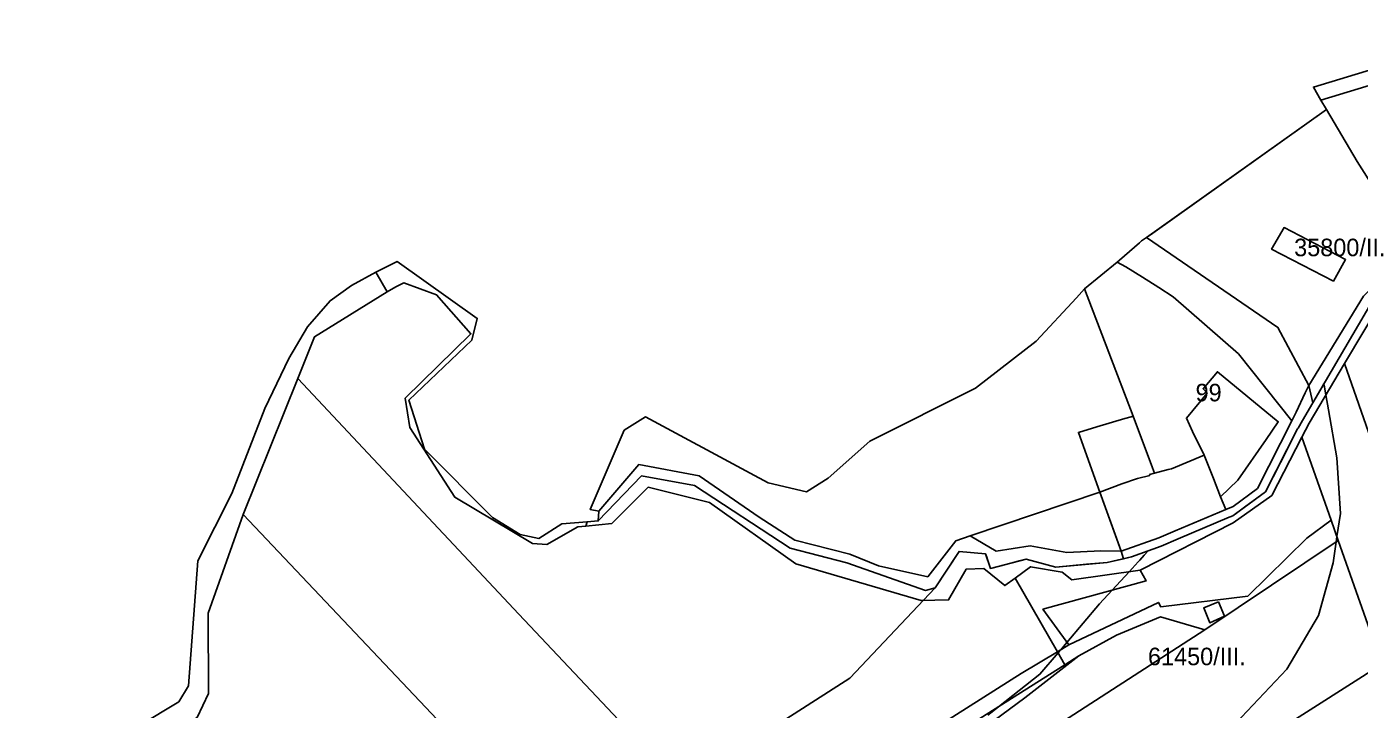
# Model space of a CAD drawing. Extents: x -522079 to -518833, y -1142400 to -1139961.
# Drawn here: x -521365.3 to -520985.3, y -1140287.7 to -1140093 of the extents above; entities that cross this region are included whole.
import ezdxf

# ---------------------------------------------------------------- set-up
doc = ezdxf.new("R2010")
doc.units = 0
for name, color, linetype in [('95560013', 7, 'Continuous'), ('95590013', 7, 'Continuous'), ('95600013', 7, 'Continuous'), ('95610013', 7, 'Continuous'), ('95630013', 7, 'Continuous'), ('95640013', 7, 'Continuous'), ('95660013', 7, 'Continuous')]:
    doc.layers.add(name, color=color, linetype=linetype)

msp = doc.modelspace()

# ---------------------------------------------------------------- linework, layer by layer
at = {"layer": '95560013'}
for points in [[(-520875.21, -1140149), (-520981.4, -1140212.45), (-520989.57, -1140189.1), (-520978.85, -1140171.05), (-520967.99, -1140160), (-520949.73, -1140132.35), (-520942.17, -1140125.91), (-520910.05, -1140126.02), (-520892.49, -1140129.42), (-520884.78, -1140137.14), (-520873.63, -1140145.32), (-520873.12, -1140147.75)], [(-521144.75, -1140380.49), (-521166.55, -1140356.84), (-521138.04, -1140336), (-521105.44, -1140313.39), (-521071.25, -1140292.13), (-521029.36, -1140265.01), (-520991.34, -1140239.5), (-520978.89, -1140274.79)], [(-521042, -1140261.25), (-521029.36, -1140265.01), (-521071.25, -1140292.13), (-521105.44, -1140313.39), (-521138.04, -1140336), (-521166.55, -1140356.84), (-521170.88, -1140360.01), (-521186.8, -1140371.65), (-521202.24, -1140382.94), (-521262.52, -1140430.5), (-521393.25, -1140533.65), (-521431, -1140563.44), (-521501.14, -1140618.78), (-521510.5, -1140608.85), (-521177.32, -1140348.18), (-521127.62, -1140312.94), (-521125.23, -1140315.3), (-521106.97, -1140303.78), (-521080.73, -1140284.42), (-521065.28, -1140272.43), (-521054.61, -1140266.48)], [(-521113.39, -1140302.86), (-521069.26, -1140274.95), (-521065.28, -1140272.43), (-521080.73, -1140284.42), (-521106.97, -1140303.78), (-521125.23, -1140315.3), (-521127.62, -1140312.94)], [(-520943.46, -1140405.56), (-520937.19, -1140417.44), (-520924.28, -1140409.64), (-520923.06, -1140411.9), (-520913.58, -1140428.33), (-520906.37, -1140439.12), (-521031.07, -1140496.4), (-521039.03, -1140495.22), (-521144.75, -1140380.49), (-520978.89, -1140274.79), (-520959.74, -1140329.07), (-520948.85, -1140357.77), (-520931.92, -1140395.43), (-520930.52, -1140398.04)]]:
    msp.add_lwpolyline(points, close=True, dxfattribs=at)
at = {"layer": '95590013'}
for points in [[(-521042.61, -1140257.18), (-521068.15, -1140269.31), (-521075.53, -1140259.14), (-521046.13, -1140251.03), (-521047.85, -1140248.01), (-521021.33, -1140234.46), (-521010.26, -1140226.65), (-521001.72, -1140210.08), (-520993.36, -1140233.77), (-521000.33, -1140238.84), (-521017.12, -1140255.44), (-521041.88, -1140258.46)], [(-521053.25, -1140242.58), (-521058.99, -1140242.45), (-521068.77, -1140242.91), (-521079.19, -1140241.03), (-521088.86, -1140242.57), (-521096.26, -1140238.22), (-521059.29, -1140225.79)]]:
    msp.add_lwpolyline(points, close=True, dxfattribs=at)
at = {"layer": '95600013'}
for points in [[(-520999.73, -1140195.29), (-521008.55, -1140178.79), (-521045.99, -1140153.16), (-520994.7, -1140116.62), (-520985.99, -1140131.48), (-520970.51, -1140155.67), (-520977.56, -1140163.28), (-520984.14, -1140169.84)], [(-521006.77, -1140150.28), (-521010.35, -1140156.42), (-520992.72, -1140165.55), (-520989.25, -1140159.42)], [(-521146.28, -1140239.39), (-521156.43, -1140232.87), (-521173.55, -1140221.12), (-521190.8, -1140217.9), (-521202.15, -1140231.14), (-521204.62, -1140230.71), (-521194.92, -1140208.09), (-521188.9, -1140204.31), (-521159.02, -1140220.32), (-521153.92, -1140223.1), (-521142.98, -1140225.64), (-521136.78, -1140221.72), (-521124.89, -1140211.23), (-521094.81, -1140196.05), (-521077.51, -1140182.69), (-521066.01, -1140170.35), (-521063.7, -1140167.77), (-521049.86, -1140204.08), (-521050.38, -1140204.23), (-521052.23, -1140204.77), (-521060.17, -1140207.15), (-521065.43, -1140208.69), (-521059.29, -1140225.79), (-521096.26, -1140238.22), (-521100.42, -1140239.62), (-521108.36, -1140249.87), (-521122.43, -1140246.78), (-521130.62, -1140243.41)]]:
    msp.add_lwpolyline(points, close=True, dxfattribs=at)
at = {"layer": '95610013'}
msp.add_lwpolyline([(-521160.13, -1140329.24), (-521224.97, -1140260.52), (-521288.02, -1140193.37), (-521283.26, -1140181.41), (-521262.49, -1140168.67), (-521260.08, -1140167.19), (-521257.73, -1140166.05), (-521248.42, -1140169.45), (-521238.63, -1140180.63), (-521257.36, -1140198.93), (-521256.03, -1140207.29), (-521243.23, -1140227.2), (-521221.12, -1140240.34), (-521217.02, -1140240.66), (-521208.19, -1140235.66), (-521205.87, -1140235.43), (-521198.5, -1140234.71), (-521188.13, -1140224.34), (-521170.61, -1140228.65), (-521146.04, -1140246.18), (-521110.27, -1140256.62), (-521102.44, -1140256.49), (-521097.42, -1140247.68), (-521092.43, -1140247.55), (-521086.36, -1140252.38), (-521083.46, -1140250.25), (-521071.39, -1140271.24), (-521081.77, -1140277.41), (-521115.76, -1140299)], dxfattribs=at)
for points in [[(-521303.57, -1140232.09), (-521288.02, -1140193.37), (-521224.97, -1140260.52), (-521160.13, -1140329.24), (-521181.05, -1140344.19), (-521190.73, -1140351.49), (-521249.83, -1140288.83)], [(-521319.77, -1140291.98), (-521316.7, -1140289.98), (-521313.45, -1140283.14), (-521313.53, -1140260.28), (-521303.57, -1140232.09), (-521249.83, -1140288.83), (-521190.73, -1140351.49), (-521212.85, -1140368.17), (-521233.39, -1140383.74), (-521281.93, -1140333.33)]]:
    msp.add_lwpolyline(points, close=True, dxfattribs=at)
at = {"layer": '95630013'}
for points in [[(-520840.13, -1140106.03), (-520833.95, -1140124.09), (-520832.38, -1140130.38), (-520834.57, -1140131.44), (-520836.28, -1140125.74), (-520838.47, -1140119.76), (-520853.61, -1140106.69), (-520870.57, -1140104.77), (-520896.13, -1140105.14), (-520930.39, -1140100.03), (-520964.33, -1140104.24), (-520996.26, -1140113.95), (-520998.41, -1140110.24), (-520941.45, -1140093.01), (-520920.41, -1140096.1), (-520898.59, -1140102.13), (-520887.39, -1140102.82), (-520865.88, -1140095.27), (-520850.56, -1140096.88)], [(-521212.75, -1140234.73), (-521205.52, -1140234.19), (-521205.87, -1140235.43), (-521208.19, -1140235.66), (-521217.02, -1140240.66), (-521221.12, -1140240.34), (-521243.23, -1140227.2), (-521256.03, -1140207.29), (-521257.36, -1140198.93), (-521238.63, -1140180.63), (-521248.42, -1140169.45), (-521257.73, -1140166.05), (-521260.08, -1140167.19), (-521262.49, -1140168.67), (-521265.75, -1140163.05), (-521259.67, -1140159.99), (-521236.81, -1140176.19), (-521238.42, -1140182.36), (-521256.3, -1140199.5), (-521251.89, -1140213.49), (-521232.49, -1140232.94), (-521224.62, -1140237.78), (-521219.26, -1140238.96)]]:
    msp.add_lwpolyline(points, close=True, dxfattribs=at)
for points in [[(-521333.16, -1140292.26), (-521321.89, -1140285.5), (-521319.14, -1140281.01), (-521316.46, -1140245.31), (-521306.79, -1140226.13), (-521297.37, -1140201.85), (-521290.54, -1140187.61), (-521285.21, -1140178.6), (-521278.81, -1140171.17), (-521272.67, -1140166.78), (-521265.75, -1140163.05), (-521262.49, -1140168.67), (-521283.26, -1140181.41), (-521288.02, -1140193.37), (-521303.57, -1140232.09), (-521313.53, -1140260.28), (-521313.45, -1140283.14), (-521316.7, -1140289.98)], [(-520978.85, -1140171.05), (-520989.57, -1140189.1), (-520999.64, -1140206.05), (-521001.72, -1140210.08), (-521010.26, -1140226.65), (-521021.33, -1140234.46), (-521047.85, -1140248.01), (-521067.28, -1140250.75), (-521070.02, -1140248.6), (-521079.08, -1140247.03), (-521083.46, -1140250.25), (-521086.36, -1140252.38), (-521092.43, -1140247.55), (-521097.42, -1140247.68), (-521102.44, -1140256.49), (-521110.27, -1140256.62), (-521146.04, -1140246.18), (-521170.61, -1140228.65), (-521188.13, -1140224.34), (-521198.5, -1140234.71), (-521205.87, -1140235.43), (-521205.52, -1140234.19), (-521202.32, -1140233.95), (-521189.97, -1140221.12), (-521174.85, -1140223.86), (-521147.64, -1140241.68), (-521131.5, -1140245.93), (-521109, -1140253.76), (-521106.23, -1140253.05), (-521099.45, -1140242.66), (-521091.88, -1140243.35), (-521090.52, -1140247.47), (-521080.35, -1140244.81), (-521071.82, -1140247.15), (-521057.24, -1140245.77), (-521050.32, -1140244.21), (-521041.79, -1140241.11), (-521036.95, -1140239.06), (-521022.45, -1140232.92), (-521021.42, -1140232.48), (-521012.11, -1140225.69), (-521002.93, -1140207.73), (-521002.8, -1140207.48), (-521001.55, -1140205.34), (-520998.6, -1140200.31), (-520997.26, -1140198.03), (-520981.64, -1140171.39)], [(-520981.64, -1140171.39), (-520997.26, -1140198.03), (-520998.6, -1140200.31), (-521001.55, -1140205.34), (-521002.8, -1140207.48), (-521002.93, -1140207.73), (-521012.11, -1140225.69), (-521021.42, -1140232.48), (-521022.45, -1140232.92), (-521036.95, -1140239.06), (-521041.79, -1140241.11), (-521050.32, -1140244.21), (-521057.24, -1140245.77), (-521071.82, -1140247.15), (-521080.35, -1140244.81), (-521090.52, -1140247.47), (-521091.88, -1140243.35), (-521099.45, -1140242.66), (-521106.23, -1140253.05), (-521109, -1140253.76), (-521131.5, -1140245.93), (-521147.64, -1140241.68), (-521174.85, -1140223.86), (-521189.97, -1140221.12), (-521202.32, -1140233.95), (-521202.15, -1140231.14), (-521190.8, -1140217.9), (-521173.55, -1140221.12), (-521156.43, -1140232.87), (-521146.28, -1140239.39), (-521130.62, -1140243.41), (-521122.43, -1140246.78), (-521108.36, -1140249.87), (-521100.42, -1140239.62), (-521096.26, -1140238.22), (-521088.86, -1140242.57), (-521079.19, -1140241.03), (-521068.77, -1140242.91), (-521058.99, -1140242.45), (-521053.25, -1140242.58), (-521042.48, -1140238.76), (-521037.86, -1140236.76), (-521023.4, -1140230.68), (-521021.33, -1140229.82), (-521014.41, -1140224.73), (-521004.56, -1140205.45), (-521003.35, -1140202.91), (-521000.75, -1140197.43), (-520999.73, -1140195.29), (-520984.14, -1140169.84)]]:
    msp.add_lwpolyline(points, dxfattribs=at)
at = {"layer": '95640013'}
for points in [[(-520985.99, -1140131.48), (-520994.7, -1140116.62), (-520996.26, -1140113.95), (-520964.33, -1140104.24), (-520930.39, -1140100.03), (-520896.13, -1140105.14), (-520870.57, -1140104.77), (-520853.61, -1140106.69), (-520838.47, -1140119.76), (-520836.28, -1140125.74), (-520840.13, -1140128.04), (-520870.79, -1140146.36), (-520871.38, -1140143.8), (-520882.74, -1140135.78), (-520891.9, -1140126.87), (-520912.67, -1140122.89), (-520943.89, -1140122.58), (-520951.79, -1140130), (-520969.72, -1140157.28), (-520970.51, -1140155.67)], [(-520989.25, -1140159.42), (-520992.72, -1140165.55), (-521010.35, -1140156.42), (-521006.77, -1140150.28)], [(-521019.82, -1140186.27), (-521038.45, -1140170.03), (-521042.52, -1140167.42), (-521047.19, -1140164.44), (-521051.86, -1140161.45), (-521054.36, -1140160.13), (-521053.72, -1140159.58), (-521048.05, -1140154.68), (-521047.4, -1140154.12), (-521045.99, -1140153.16), (-521008.55, -1140178.79), (-520999.73, -1140195.29), (-521000.75, -1140197.43), (-521003.35, -1140202.91), (-521004.56, -1140205.45)], [(-521043.73, -1140220.34), (-521044.31, -1140218.8), (-521049.86, -1140204.08), (-521063.7, -1140167.77), (-521054.36, -1140160.13), (-521051.86, -1140161.45), (-521047.19, -1140164.44), (-521042.52, -1140167.42), (-521038.45, -1140170.03), (-521019.82, -1140186.27), (-521004.56, -1140205.45), (-521014.41, -1140224.73), (-521021.33, -1140229.82), (-521023.4, -1140230.68), (-521024.94, -1140227.06), (-521019.95, -1140222.33), (-521011.89, -1140210.69), (-521008.43, -1140205.69), (-521025.79, -1140191.41), (-521029.89, -1140196.26), (-521028.73, -1140197.48), (-521034.61, -1140204.63), (-521032.9, -1140208.45), (-521029.59, -1140215.24), (-521038.87, -1140219.06), (-521039.84, -1140219.26)], [(-521034.61, -1140204.63), (-521028.73, -1140197.48), (-521029.89, -1140196.26), (-521025.79, -1140191.41), (-521008.43, -1140205.69), (-521011.89, -1140210.69), (-521019.95, -1140222.33), (-521024.94, -1140227.06), (-521026.94, -1140221.87), (-521029.59, -1140215.24), (-521032.9, -1140208.45)], [(-521059.29, -1140225.79), (-521065.43, -1140208.69), (-521060.17, -1140207.15), (-521052.23, -1140204.77), (-521050.38, -1140204.23), (-521049.86, -1140204.08), (-521044.31, -1140218.8), (-521043.73, -1140220.34), (-521045.13, -1140220.72), (-521045.07, -1140220.96), (-521048.62, -1140221.83), (-521053.03, -1140223.33)], [(-521045.13, -1140220.72), (-521043.73, -1140220.34), (-521039.84, -1140219.26), (-521038.87, -1140219.06), (-521029.59, -1140215.24), (-521026.94, -1140221.87), (-521024.94, -1140227.06), (-521023.4, -1140230.68), (-521037.86, -1140236.76), (-521042.48, -1140238.76), (-521053.25, -1140242.58), (-521059.29, -1140225.79), (-521053.03, -1140223.33), (-521048.62, -1140221.83), (-521045.07, -1140220.96)], [(-521029.36, -1140265.01), (-521042, -1140261.25), (-521054.61, -1140266.48), (-521065.28, -1140272.43), (-521069.26, -1140274.95), (-521071.39, -1140271.24), (-521068.15, -1140269.31), (-521042.61, -1140257.18), (-521041.88, -1140258.46), (-521017.12, -1140255.44), (-521000.33, -1140238.84), (-520993.36, -1140233.77), (-520991.34, -1140239.5)], [(-521071.39, -1140271.24), (-521083.46, -1140250.25), (-521079.08, -1140247.03), (-521070.02, -1140248.6), (-521067.28, -1140250.75), (-521047.85, -1140248.01), (-521046.13, -1140251.03), (-521075.53, -1140259.14), (-521068.15, -1140269.31)], [(-521025.45, -1140257.06), (-521023.8, -1140261.15), (-521027.96, -1140262.97), (-521029.71, -1140258.76)], [(-521025.45, -1140257.06), (-521029.71, -1140258.76), (-521027.96, -1140262.97), (-521023.8, -1140261.15)], [(-521115.76, -1140299), (-521081.77, -1140277.41), (-521071.39, -1140271.24), (-521069.26, -1140274.95), (-521113.39, -1140302.86), (-521127.62, -1140312.94), (-521130.86, -1140309.33)]]:
    msp.add_lwpolyline(points, close=True, dxfattribs=at)
msp.add_lwpolyline([(-520978.89, -1140274.79), (-520991.34, -1140239.5), (-520993.36, -1140233.77), (-521001.72, -1140210.08), (-520999.64, -1140206.05), (-520989.57, -1140189.1), (-520981.4, -1140212.45)], dxfattribs=at)
at = {"layer": '95660013'}
for points in [[(-520970.51, -1140155.67), (-520985.99, -1140131.48), (-520994.7, -1140116.62), (-520996.26, -1140113.95), (-520998.41, -1140110.24), (-520941.45, -1140093.01)], [(-521333.16, -1140292.26), (-521321.89, -1140285.5), (-521319.14, -1140281.01), (-521316.46, -1140245.31), (-521306.79, -1140226.13), (-521297.37, -1140201.85), (-521290.54, -1140187.61), (-521285.21, -1140178.6), (-521278.81, -1140171.17), (-521272.67, -1140166.78), (-521265.75, -1140163.05), (-521259.67, -1140159.99), (-521236.81, -1140176.19), (-521238.42, -1140182.36), (-521256.3, -1140199.5), (-521251.89, -1140213.49), (-521232.49, -1140232.94), (-521224.62, -1140237.78), (-521219.26, -1140238.96), (-521212.75, -1140234.73), (-521205.52, -1140234.19), (-521202.32, -1140233.95), (-521202.15, -1140231.14), (-521204.62, -1140230.71), (-521194.92, -1140208.09), (-521188.9, -1140204.31), (-521159.02, -1140220.32), (-521153.92, -1140223.1), (-521142.98, -1140225.64), (-521136.78, -1140221.72), (-521124.89, -1140211.23), (-521094.81, -1140196.05), (-521077.51, -1140182.69), (-521066.01, -1140170.35), (-521063.7, -1140167.77), (-521049.86, -1140204.08), (-521050.38, -1140204.23), (-521052.23, -1140204.77), (-521060.17, -1140207.15), (-521065.43, -1140208.69), (-521059.29, -1140225.79), (-521055.82, -1140235.43), (-521053.25, -1140242.58), (-521052.54, -1140244.71), (-521057.24, -1140245.77), (-521063.1, -1140246.32), (-521071.82, -1140247.15), (-521075.39, -1140246.17), (-521080.35, -1140244.81), (-521082.35, -1140245.33), (-521083.25, -1140245.57), (-521087.96, -1140246.8), (-521090.52, -1140247.47), (-521091.26, -1140245.22), (-521091.58, -1140244.27), (-521091.88, -1140243.35), (-521099.45, -1140242.66), (-521100.22, -1140243.84), (-521106.23, -1140253.05), (-521130.6, -1140278.79), (-521148.82, -1140290.47)], [(-521020.52, -1140291.59), (-521006.02, -1140276.26), (-520996.96, -1140260.94), (-520992.81, -1140245.87), (-520991.93, -1140239.9), (-520991.71, -1140238.43), (-520990.74, -1140231.84), (-520991.78, -1140216), (-520994.11, -1140202.23), (-520994.85, -1140198), (-520995.34, -1140195.22), (-520995.41, -1140194.88), (-520995.24, -1140194.59), (-520994.97, -1140194.13), (-520981.64, -1140171.39)], [(-521091.26, -1140289.33), (-521088.2, -1140286.93), (-521076.41, -1140277.68), (-521071.21, -1140271.55), (-521070.83, -1140271.1), (-521070.48, -1140270.7), (-521068.68, -1140268.58), (-521059.39, -1140257.63), (-521055.79, -1140253.69), (-521051, -1140248.45), (-521048.39, -1140245.6), (-521048.14, -1140245.34), (-521047.94, -1140245.12), (-521046.67, -1140243.72), (-521045.54, -1140242.47), (-521041.79, -1140241.11), (-521036.95, -1140239.06), (-521022.45, -1140232.92), (-521021.86, -1140232.66), (-521021.42, -1140232.48), (-521018.03, -1140230.01), (-521012.11, -1140225.69), (-521007.83, -1140217.32), (-521003.4, -1140208.66), (-521002.92, -1140207.71), (-521002.8, -1140207.48), (-521001.55, -1140205.34), (-520998.6, -1140200.31), (-520998.32, -1140199.84), (-520997.26, -1140198.03), (-520996, -1140195.88), (-520995.41, -1140194.88), (-520995.34, -1140195.22), (-520994.85, -1140198), (-520994.11, -1140202.23), (-520991.78, -1140216), (-520990.74, -1140231.84), (-520991.71, -1140238.43), (-520991.93, -1140239.9), (-520992.81, -1140245.87), (-520996.96, -1140260.94), (-521006.02, -1140276.26), (-521020.52, -1140291.59)], [(-521148.82, -1140290.47), (-521130.6, -1140278.79), (-521106.23, -1140253.05), (-521100.22, -1140243.84), (-521099.45, -1140242.66), (-521091.88, -1140243.35), (-521091.58, -1140244.27), (-521091.26, -1140245.22), (-521090.52, -1140247.47), (-521087.96, -1140246.8), (-521083.25, -1140245.57), (-521082.35, -1140245.33), (-521080.35, -1140244.81), (-521075.39, -1140246.17), (-521071.82, -1140247.15), (-521063.1, -1140246.32), (-521057.24, -1140245.77), (-521052.54, -1140244.71), (-521050.32, -1140244.21), (-521045.54, -1140242.47), (-521046.67, -1140243.72), (-521047.94, -1140245.12), (-521048.14, -1140245.34), (-521048.39, -1140245.6), (-521051, -1140248.45), (-521055.79, -1140253.69), (-521059.39, -1140257.63), (-521068.68, -1140268.58), (-521070.48, -1140270.7), (-521070.83, -1140271.1), (-521071.21, -1140271.55), (-521076.41, -1140277.68), (-521088.2, -1140286.93), (-521091.26, -1140289.33)]]:
    msp.add_lwpolyline(points, dxfattribs=at)
for points in [[(-520969.27, -1140158.18), (-520976.2, -1140164.63), (-520981.64, -1140171.39), (-520994.97, -1140194.13), (-520995.24, -1140194.59), (-520995.41, -1140194.88), (-520996, -1140195.88), (-520997.26, -1140198.03), (-520998.32, -1140199.84), (-520998.6, -1140200.31), (-520999.73, -1140195.29), (-521008.55, -1140178.79), (-521045.99, -1140153.16), (-521044.19, -1140151.88), (-520994.7, -1140116.62), (-520985.99, -1140131.48), (-520970.51, -1140155.67), (-520969.72, -1140157.28)], [(-521045.99, -1140153.16), (-521008.55, -1140178.79), (-520999.73, -1140195.29), (-520998.6, -1140200.31), (-521001.55, -1140205.34), (-521002.8, -1140207.48), (-521002.92, -1140207.71), (-521003.4, -1140208.66), (-521007.83, -1140217.32), (-521012.11, -1140225.69), (-521018.03, -1140230.01), (-521021.42, -1140232.48), (-521021.86, -1140232.66), (-521022.45, -1140232.92), (-521036.95, -1140239.06), (-521041.79, -1140241.11), (-521045.54, -1140242.47), (-521050.32, -1140244.21), (-521052.54, -1140244.71), (-521053.25, -1140242.58), (-521055.82, -1140235.43), (-521059.29, -1140225.79), (-521065.43, -1140208.69), (-521060.17, -1140207.15), (-521052.23, -1140204.77), (-521050.38, -1140204.23), (-521049.86, -1140204.08), (-521063.7, -1140167.77), (-521054.36, -1140160.13), (-521053.72, -1140159.58), (-521048.05, -1140154.68), (-521047.4, -1140154.12)]]:
    msp.add_lwpolyline(points, close=True, dxfattribs=at)

# ---------------------------------------------------------------- texts
for s, rotation, p in [('35800/II.', 360, (-521003.91, -1140158.47)), ('99', 0, (-521032.02, -1140199.85)), ('61450/III.', 360, (-521045.59, -1140275.09))]:
    msp.add_text(s, height=5, rotation=rotation, dxfattribs=at).set_placement(p)

doc.saveas('drawing.dxf')
